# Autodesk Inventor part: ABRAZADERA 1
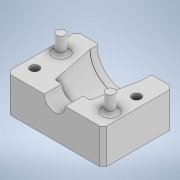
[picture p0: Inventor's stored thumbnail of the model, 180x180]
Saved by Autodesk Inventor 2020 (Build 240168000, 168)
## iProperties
Created: 2022-10
Part Number: ABRAZADERA 1
Material: Genérico
Document SubType Name: Modeling
Designer: SEBAS
Density: 1 g/cm^3
Appearance: Valor por defecto
Author: SEBAS
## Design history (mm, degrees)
sketch "Boceto1"
  geometry: L1 (0, 0)-(0, 40); L2 (0, 40)-(33, 40); L3 (33, 40)-(33, 30); L4 (33, 30)-(23, 30); L5 (23, 30)-(18, 5); L6 (18, 5)-(18, 0); L7 (18, 0)-(0, 0); L8 (33, 40)-(33, 0)
  constraints: 16 end point, 3 perpendicular, 2 horizontal, 2 vertical
  dimensions: "d0" = 40 distance of L1.start L1.end; "d1" = 10 distance of L2.end L3.end; "d2" = 5 horizontal distance of L4.end L5.end; "d3" = 25 vertical distance of L5.end L4.end; "d4" = 33 distance between parallel lines of L1 L3; "d5" = 18 distance of L1.start L6.end
revolve "Revolución1" sketch "Boceto1" stored, may be unused: angle "d6" = 180 deg
sketch "Boceto2"
  geometry: L1 (10, 0)-(-10, 0) reference; C1 r 6 at (0, 0); 3 further points
  constraints: 1 centre point, 1 midpoint
  dimensions: "d7" = 12 diameter of C1
extrude "Extrusión1" cut sketch "Boceto2" distance "d8" = 10; taper "d9" = 0 deg
sketch "Boceto3"
  geometry: L1 (11.5, -15)-(54.5, -15); C1 r 2.5 at (11.5, -15); C2 r 2.5 at (11.5, -30); C3 r 2.5 at (54.5, -15); C4 r 2.5 at (54.5, -30); 2 further points
  constraints: 4 centre point, 3 equal radius, 3 vertical alignment, 2 end point, 2 horizontal alignment, 1 horizontal, 1 midpoint
  dimensions: "d10" = 5 diameter of C1; "d11" = 15 vertical distance of point (33, 0) L1.start; "d12" = 15 distance of C2.centre L1.start; "d13" = 43 distance of L1.end L1.start
extrude "Extrusión2" join sketch "Boceto3" distance "d14" = 10; taper "d15" = 0 deg
extrude "Extrusión3" cut sketch "Boceto3" distance "d16" = 30; taper "d17" = 0 deg
sketch "Boceto4"
  geometry: L1 (66, 0)-(0, 0); L2 (0, 0)-(0, -20); L3 (0, -20)-(66, -20); L4 (66, -20)-(66, 0); L5 (66, -20)-(0, -20); L6 (0, -20)-(0, -39); L7 (0, -39)-(66, -39); L8 (66, -39)-(66, -20); A1 r 33 centre (33, 0) between (0, 0) and (66, 0) reference; 4 further points
  constraints: 16 end point, 4 parallel, 2 horizontal, 2 perpendicular, 1 tangent, 1 vertical alignment
  dimensions: "d18" = 20 distance of L3.end L1.start; "d19" = 19 distance of L7.end L3.end
extrude "Extrusión4" cut sketch "Boceto4" stored distance "d20" = 30; taper "d21" = 0 deg
extrude "Extrusión5" join sketch "Boceto4" stored distance "d22" = 30; taper "d23" = 0 deg
sketch "Boceto5"
  geometry: L1 (33, 0)-(6, 0) reference; L2 (-33, -20)-(33, -20) reference; L3 (27.5, 0)-(-27.5, 0); L4 (-27.5, 0)-(-27.5, -20); L5 (-27.5, -20)-(27.5, -20); L6 (27.5, -20)-(27.5, 0); L7 (33, -20)-(27.5, -20); L8 (27.5, -20)-(27.5, 0); L9 (27.5, 0)-(33, 0); L10 (33, 0)-(33, -20); L11 (-27.5, -20)-(-33, -20); L12 (-33, -20)-(-33, 0); L13 (-33, 0)-(-27.5, 0); L14 (-27.5, 0)-(-27.5, -20); L15 (-33, 0)-(-33, -20) reference; 7 further points
  constraints: 24 end point, 6 parallel, 3 horizontal, 3 perpendicular, 3 point on line, 2 midpoint, 1 coincident, 1 vertical alignment
  dimensions: "d24" = 55 distance between parallel lines of L4 L6
extrude "Extrusión6" cut sketch "Boceto5" stored distance "d25" = 30; taper "d26" = 0 deg
fillet "Empalme1" dims "d30" = 2
fillet "Empalme2" dims "d31" = 1
chamfer "Chaflán2" distance "d32" = 2; stored, may be unused: second distance "d33" = 2, angle "d34" = 45 deg
node "Sólido1"
